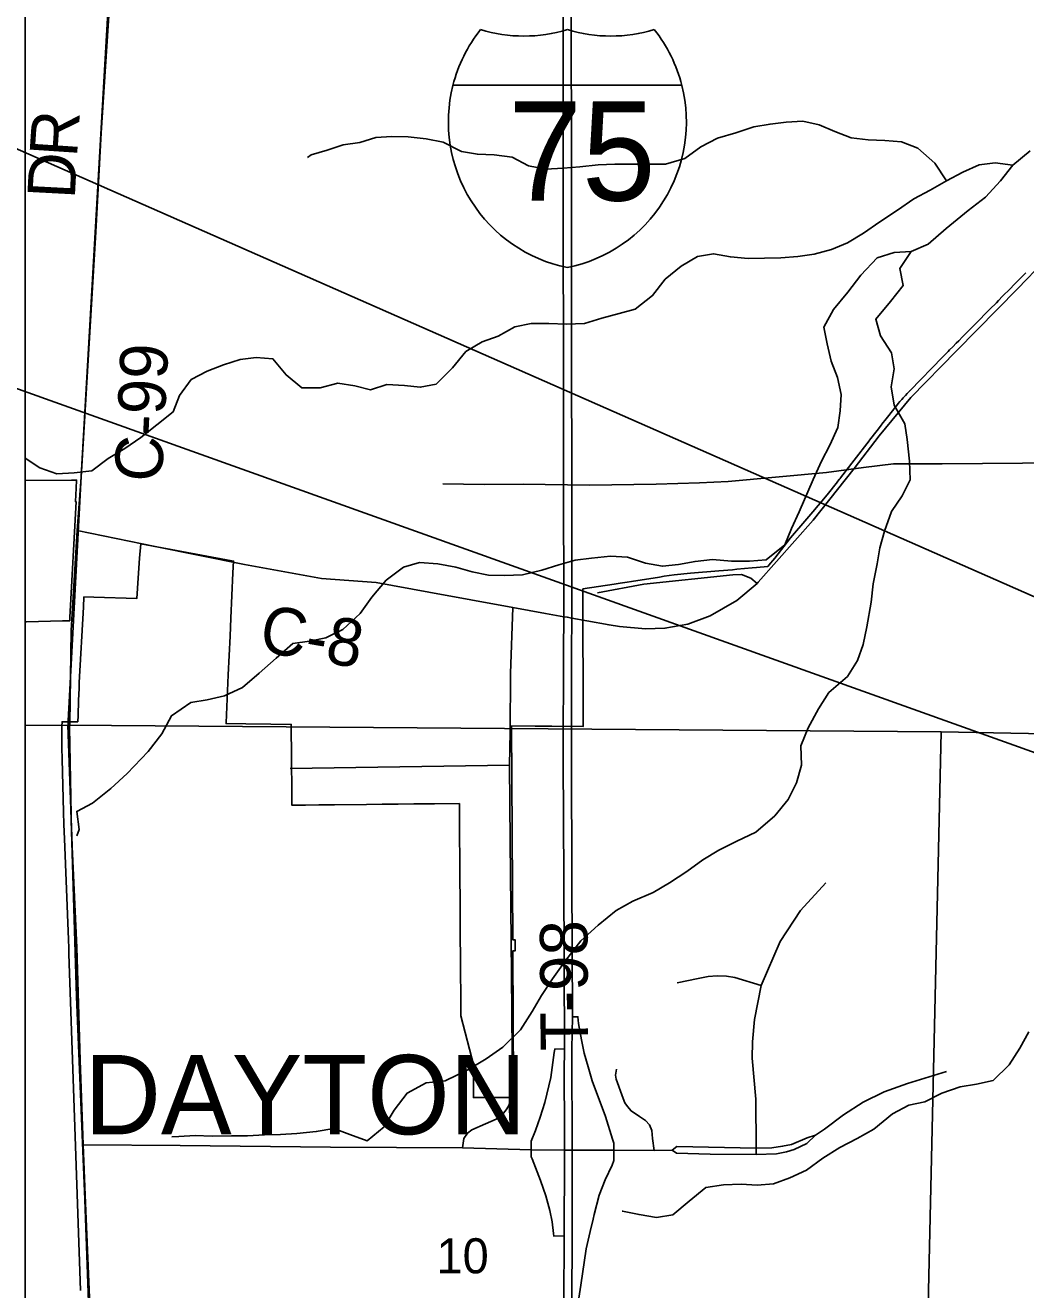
# Model space of a CAD drawing. Extents: x -38.1 to 35.9, y -2.7 to 28.5.
# Drawn here: x 8.115 to 9.309, y 16.206 to 17.716 of the extents above; entities that cross this region are included whole.
import ezdxf

# ---------------------------------------------------------------- set-up
doc = ezdxf.new("R2010")
doc.units = 0
for name, color, linetype in [('GM_X_City_Street', 7, 'Continuous'), ('GM_X_City_Street_Text', 7, 'Continuous'), ('GM_X_Corporation', 7, 'Continuous'), ('GM_X_Corporation_Text', 7, 'Continuous'), ('GM_X_Interstate_Route', 7, 'Continuous'), ('GM_X_Major_River_Text', 7, 'Continuous'), ('GM_X_Minor_Lake', 7, 'Continuous'), ('GM_X_Minor_River', 7, 'Continuous'), ('GM_X_Rail_Line_Text', 7, 'Continuous'), ('GM_X_Section', 7, 'Continuous'), ('GM_X_State_Route', 7, 'Continuous'), ('GM_X_Township', 7, 'Continuous'), ('GM_X_Township_Subdivision', 7, 'Continuous'), ('GM_X_US_Route', 7, 'Continuous'), ('SH_Data', 7, 'Continuous')]:
    doc.layers.add(name, color=color, linetype=linetype)

msp = doc.modelspace()

# ---------------------------------------------------------------- linework, layer by layer
at = {"layer": 'GM_X_City_Street'}
for points in [[(8.798, 17.0381), (8.8534, 17.0482), (8.9596, 17.0594), (8.9699, 17.0598), (8.981, 17.0557), (8.9885, 17.0492)], [(8.9876, 16.3675), (8.9876, 16.3751), (8.9871, 16.4337), (8.9828, 16.4825), (8.9832, 16.5018), (8.9855, 16.5288), (8.9933, 16.5692), (9.0162, 16.6217), (9.0403, 16.6586), (9.0705, 16.6917)], [(8.8931, 16.5725), (8.9183, 16.5775), (8.9302, 16.5798), (8.9408, 16.5808), (8.9522, 16.5802), (8.962, 16.5786), (8.9933, 16.5692)], [(8.8656, 16.3723), (8.8638, 16.3864), (8.8627, 16.3963), (8.86, 16.4027), (8.8554, 16.4079), (8.8481, 16.4128), (8.838, 16.4195), (8.8339, 16.4247), (8.8306, 16.4292), (8.8285, 16.4342), (8.8203, 16.4573), (8.8196, 16.4622), (8.8206, 16.4695)], [(9.0585, 16.3907), (9.069, 16.3978), (9.0917, 16.4148), (9.1153, 16.4299), (9.1404, 16.4422), (9.1683, 16.4522), (9.2147, 16.4664)], [(8.1838, 16.379), (8.2995, 16.3784), (8.4793, 16.3764), (8.6368, 16.3753)], [(8.8873, 16.3728), (8.8923, 16.3689), (8.9327, 16.368), (8.9876, 16.3675), (9.0117, 16.3684), (9.0235, 16.3708), (9.033, 16.3736), (9.0481, 16.3807), (9.0585, 16.3907)], [(8.8873, 16.3728), (8.8926, 16.377), (8.9876, 16.3751), (9.0061, 16.3756), (9.019, 16.3773), (9.0297, 16.3796), (9.0483, 16.3872), (9.0585, 16.3907)], [(8.6368, 16.3753), (8.7187, 16.3731), (8.7587, 16.3728), (8.7629, 16.3727), (8.7677, 16.3727), (8.8175, 16.3727)], [(8.8175, 16.3727), (8.8656, 16.3723), (8.8873, 16.3728)]]:
    msp.add_lwpolyline(points, dxfattribs=at)
at = {"layer": 'GM_X_City_Street_Text'}
for points in [[(8.1677, 16.8817), (8.1695, 16.9932), (8.1765, 17.1126), (8.1815, 17.1762), (8.1988, 17.4691), (8.2052, 17.587), (8.2104, 17.6664), (8.2151, 17.7391), (8.2187, 17.7863), (8.2231, 17.868), (8.2231, 17.8756)], [(8.9898, 17.0507), (9.0554, 17.1249), (9.1046, 17.1865), (9.1345, 17.2256), (9.1723, 17.2711), (9.2266, 17.3269), (9.3001, 17.4015), (9.3314, 17.4339), (9.3361, 17.4389)], [(8.1765, 17.1126), (8.2697, 17.0932), (8.3766, 17.0717), (8.4684, 17.055), (8.5336, 17.0502), (8.5967, 17.0387)], [(8.7852, 17.0046), (8.8119, 16.9997), (8.8241, 16.9977), (8.8552, 16.9952), (8.8785, 16.9958), (8.906, 17.0008), (8.9325, 17.0106), (8.9643, 17.0288), (8.9885, 17.0492), (8.9898, 17.0507)], [(8.5967, 17.0387), (8.6968, 17.0205), (8.736, 17.0133)], [(8.736, 17.0133), (8.7576, 17.0093), (8.7619, 17.009), (8.7674, 17.0079), (8.7852, 17.0046)], [(8.1924, 16.1683), (8.1862, 16.3191), (8.1838, 16.379), (8.18, 16.4801), (8.1761, 16.6146), (8.17, 16.7523), (8.1676, 16.8777), (8.1677, 16.8817)]]:
    msp.add_lwpolyline(points, dxfattribs=at)
at = {"layer": 'GM_X_Corporation'}
for points in [[(8.1169, 12.9308), (8.1202, 13.4509), (8.1267, 14.3761), (8.1272, 14.5808), (8.1295, 14.9033), (8.1448, 15.2944), (8.1561, 15.4105), (8.2031, 15.8872), (8.1758, 16.5559), (8.1657, 16.8852), (8.1819, 17.1843), (8.2212, 17.8697), (8.2224, 17.8749)], [(9.4498, 17.1939), (9.2095, 17.1922), (9.1516, 17.1919), (9.1158, 17.1876), (9.0714, 17.1817), (8.954, 17.1708), (8.9198, 17.1692), (8.8679, 17.1679), (8.7886, 17.1666), (8.7094, 17.1679), (8.6627, 17.1675), (8.6134, 17.1682)]]:
    msp.add_lwpolyline(points, dxfattribs=at)
at = {"layer": 'GM_X_Corporation_Text'}
msp.add_line((8.767, 16.8614), (8.767, 16.8813), dxfattribs=at)
for points in [[(8.7584, 16.4935), (8.7576, 16.6966), (8.7571, 16.8386), (8.7573, 16.969), (8.7576, 17.0093), (8.7576, 17.0139), (8.7575, 17.1756), (8.7573, 17.3174), (8.7571, 17.4714), (8.7571, 17.6068), (8.7568, 17.6716), (8.7567, 17.7848), (8.7566, 17.8702)], [(8.767, 16.8813), (8.7671, 16.9689), (8.7674, 17.0079), (8.7675, 17.0138), (8.7673, 17.1755), (8.7671, 17.3173), (8.767, 17.4713), (8.767, 17.6067), (8.7666, 17.6715), (8.7665, 17.7847), (8.7664, 17.8701)], [(8.7675, 16.191), (8.7679, 16.2705), (8.7678, 16.3654), (8.7677, 16.3727), (8.7676, 16.3973), (8.7673, 16.4664), (8.7675, 16.4935), (8.7683, 16.5318), (8.7675, 16.6965), (8.767, 16.8385), (8.767, 16.8614)], [(8.7594, 15.2455), (8.7597, 15.3293), (8.7594, 15.4349), (8.759, 15.5044), (8.759, 15.5824), (8.7589, 15.6629), (8.7589, 15.712), (8.7588, 15.7195), (8.7585, 15.7349), (8.7589, 15.8455), (8.759, 15.8997), (8.7587, 15.9265), (8.759, 16.0287), (8.758, 16.1522), (8.7577, 16.1907), (8.7582, 16.2702), (8.7587, 16.3653), (8.7587, 16.3728), (8.7586, 16.3972), (8.7582, 16.4663), (8.7584, 16.4935)]]:
    msp.add_lwpolyline(points, dxfattribs=at)
at = {"layer": 'GM_X_Interstate_Route'}
for p, q in [((8.6254, 17.6439), (8.8986, 17.6439)), ((8.8986, 17.6439), (8.6254, 17.6439)), ((8.8986, 17.6439), (8.6254, 17.6439))]:
    msp.add_line(p, q, dxfattribs=at)
for centre, start, end in [((8.7975, 17.6003), 141.669, 165.8066), ((8.7101, 17.8803), 253.0091, 286.9909), ((8.8139, 17.8803), 253.0091, 286.9909), ((8.7265, 17.6003), 14.1934, 38.331), ((8.7975, 17.6003), 165.8066, 258.463), ((8.7265, 17.6003), 281.537, 14.1934)]:
    msp.add_arc(centre, 0.1776, start, end, dxfattribs=at)
at = {"layer": 'GM_X_Major_River_Text'}
msp.add_line((8.4309, 16.8281), (8.6929, 16.8323), dxfattribs=at)
for points in [[(8.696, 16.4401), (8.6962, 16.4889), (8.6953, 16.5831), (8.6936, 16.741), (8.6929, 16.8323), (8.6936, 16.8715), (8.6941, 16.9419), (8.6968, 17.0205)], [(8.6368, 16.3753), (8.6384, 16.3865), (8.6426, 16.3931), (8.6478, 16.397), (8.6643, 16.4041), (8.677, 16.4096), (8.6841, 16.4149), (8.6891, 16.4209), (8.6918, 16.4253), (8.6959, 16.4369), (8.696, 16.4401)]]:
    msp.add_lwpolyline(points, dxfattribs=at)
at = {"layer": 'GM_X_Rail_Line_Text'}
for points in [[(8.8175, 16.3727), (8.8175, 16.3808), (8.816, 16.3859), (8.8076, 16.4129), (8.7917, 16.4554), (8.7867, 16.4723), (8.782, 16.4885), (8.7788, 16.5042), (8.7754, 16.5238), (8.7746, 16.5319), (8.7683, 16.5318)], [(8.7584, 16.4935), (8.7469, 16.4934), (8.7464, 16.4891), (8.7422, 16.4593), (8.7351, 16.4296), (8.7295, 16.4121), (8.7239, 16.3963), (8.7186, 16.3834), (8.7187, 16.3731)], [(8.7187, 16.3731), (8.7188, 16.3648), (8.7201, 16.3621), (8.7301, 16.3366), (8.7362, 16.3181), (8.7409, 16.3008), (8.7438, 16.2872), (8.7456, 16.2733), (8.7459, 16.2698), (8.7582, 16.2702)], [(8.7929, 16.2904), (8.7942, 16.2957), (8.8001, 16.3189), (8.8073, 16.3371), (8.8155, 16.3548), (8.8174, 16.3603), (8.8175, 16.3727)], [(8.7675, 16.191), (8.7749, 16.1906), (8.7779, 16.2116), (8.7846, 16.2547), (8.7892, 16.2756), (8.7929, 16.2904)]]:
    msp.add_lwpolyline(points, dxfattribs=at)
at = {"layer": 'GM_X_Section'}
msp.add_line((8.132, 17.1873), (8.1146, 17.1986), dxfattribs=at)
for points in [[(9.2147, 17.5299), (9.201, 17.5508), (9.1804, 17.569), (9.1611, 17.5763), (9.1413, 17.5782), (9.1211, 17.5789), (9.101, 17.5812), (9.0816, 17.5888), (9.0626, 17.5968), (9.0432, 17.601), (9.0234, 17.5999), (9.004, 17.5976), (8.9846, 17.5942), (8.9633, 17.5873), (8.9413, 17.5809), (8.9215, 17.5706), (8.9021, 17.5566), (8.8793, 17.5497), (8.8188, 17.5497), (8.7987, 17.549), (8.777, 17.5467), (8.7568, 17.5452), (8.7363, 17.5437), (8.7154, 17.5479), (8.696, 17.5581), (8.6747, 17.5608), (8.6545, 17.5616), (8.6355, 17.565), (8.6138, 17.576), (8.5933, 17.5802), (8.572, 17.5825), (8.5522, 17.5829), (8.5332, 17.5817), (8.5142, 17.5756), (8.4944, 17.573), (8.475, 17.5665), (8.456, 17.5608), (8.4518, 17.5578)], [(9.3147, 17.5656), (9.2941, 17.5485), (9.2728, 17.5515), (9.2538, 17.5489), (9.2344, 17.5401), (9.2147, 17.5299), (9.1953, 17.5189), (9.1759, 17.5082), (9.1561, 17.4949), (9.1352, 17.4809), (9.1158, 17.4676), (9.0964, 17.4558), (9.0774, 17.4478), (9.0568, 17.4425), (9.0371, 17.4395), (9.0169, 17.438), (8.9781, 17.4372), (8.9568, 17.4391), (8.9367, 17.4429), (8.9173, 17.4395), (8.8979, 17.4281), (8.8789, 17.4125), (8.8637, 17.3928), (8.8431, 17.3768), (8.8237, 17.3715), (8.8032, 17.3658), (8.7823, 17.3594), (8.761, 17.3586), (8.7397, 17.3597), (8.7188, 17.3594), (8.6994, 17.3556), (8.6792, 17.3446), (8.6602, 17.3377), (8.6408, 17.3263), (8.6249, 17.3066), (8.6055, 17.2872), (8.5864, 17.2834), (8.5674, 17.2857), (8.5465, 17.2868), (8.5271, 17.2804), (8.5081, 17.2853), (8.488, 17.2883), (8.4667, 17.2827), (8.445, 17.2827), (8.426, 17.2982), (8.4104, 17.3172), (8.3902, 17.3191), (8.3712, 17.3165), (8.3514, 17.3104), (8.3317, 17.3028), (8.3126, 17.2926), (8.299, 17.2736), (8.2913, 17.2542), (8.2716, 17.2386), (8.2526, 17.2234), (8.2335, 17.2105), (8.2138, 17.1983), (8.194, 17.1835), (8.1731, 17.1812), (8.1525, 17.1801), (8.132, 17.1873)], [(9.2941, 17.5485), (9.2793, 17.5299), (9.2614, 17.5105), (9.2405, 17.4945), (9.2143, 17.4729), (9.193, 17.4543), (9.1725, 17.4455), (9.1523, 17.4444), (9.1321, 17.4379), (9.1124, 17.4174), (9.0968, 17.3969), (9.08, 17.3764), (9.0683, 17.3551), (9.0721, 17.3353), (9.077, 17.3144), (9.0846, 17.295), (9.0888, 17.2749), (9.0876, 17.2551), (9.085, 17.2354), (9.0755, 17.2145), (9.0656, 17.1951), (9.0557, 17.1735), (9.039, 17.1347), (9.0298, 17.1149), (9.0215, 17.0952), (8.9994, 17.0773), (8.9796, 17.0758), (8.958, 17.0758), (8.9352, 17.0777), (8.9146, 17.0755), (8.8948, 17.072), (8.8755, 17.0698), (8.8553, 17.0736), (8.834, 17.0804), (8.8135, 17.0816), (8.7907, 17.0793), (8.7713, 17.077), (8.7519, 17.0713), (8.7317, 17.0649), (8.7085, 17.0596), (8.6868, 17.0588), (8.6678, 17.0592), (8.6484, 17.063), (8.6287, 17.0687), (8.6074, 17.0725), (8.5853, 17.0744), (8.5663, 17.0687), (8.5458, 17.0531), (8.5286, 17.033), (8.5146, 17.0132), (8.494, 16.9943), (8.4735, 16.9844), (8.4541, 16.9802), (8.434, 16.9775), (8.4142, 16.9601), (8.394, 16.9422), (8.3739, 16.9251), (8.3526, 16.9149), (8.3317, 16.9103), (8.3123, 16.9069), (8.2894, 16.8913), (8.2777, 16.8697), (8.2613, 16.8484), (8.2362, 16.8222), (8.2168, 16.8043), (8.1951, 16.7869), (8.1761, 16.777), (8.1788, 16.7553), (8.1761, 16.7481)], [(9.1725, 17.4455), (9.1591, 17.4254), (9.1629, 17.4049), (9.1477, 17.3859), (9.1302, 17.3646), (9.1359, 17.3448), (9.1492, 17.3247), (9.1523, 17.3053), (9.1485, 17.284), (9.1523, 17.262), (9.1652, 17.2399), (9.1679, 17.2209), (9.1705, 17.1951), (9.1713, 17.173), (9.1618, 17.154), (9.1492, 17.135), (9.1409, 17.1115), (9.1352, 17.0917), (9.1318, 17.0727), (9.1272, 17.0488), (9.1249, 17.0268), (9.1196, 16.9975), (9.1154, 16.9762), (9.1086, 16.9572), (9.0964, 16.9382), (9.0743, 16.9189), (9.0618, 16.8995), (9.0496, 16.8767), (9.0409, 16.8554), (9.0416, 16.8322), (9.0356, 16.8113), (9.0257, 16.7912), (9.0097, 16.7718), (8.9869, 16.7521), (8.9644, 16.7414), (8.9428, 16.7308), (8.9238, 16.7194), (8.9047, 16.7054), (8.8838, 16.6917), (8.8644, 16.6803), (8.8401, 16.6701), (8.8203, 16.6587), (8.7987, 16.6412), (8.7781, 16.6226), (8.7602, 16.5994), (8.7443, 16.577), (8.7313, 16.5573), (8.7199, 16.5383), (8.7059, 16.5162), (8.685, 16.4957), (8.6652, 16.4817), (8.6431, 16.4684), (8.6161, 16.4555), (8.5933, 16.4532), (8.5705, 16.4407), (8.5553, 16.4202), (8.5431, 16.4004), (8.523, 16.3837), (8.5024, 16.3913), (8.483, 16.3985), (8.4621, 16.3948), (8.4389, 16.3925), (8.4195, 16.3913), (8.4005, 16.391), (8.38, 16.3898), (8.361, 16.3898), (8.3378, 16.3895), (8.3176, 16.3902), (8.2982, 16.3891), (8.2895, 16.3887)], [(9.3132, 16.5141), (9.3025, 16.4944), (9.2896, 16.4746), (9.2706, 16.456), (9.2504, 16.4515), (9.231, 16.4481), (9.209, 16.4408), (9.1888, 16.4302), (9.1698, 16.4264), (9.1504, 16.4162), (9.128, 16.3976), (9.1082, 16.3865), (9.0873, 16.3759), (9.0671, 16.363), (9.0474, 16.3486), (9.0276, 16.3395), (9.0082, 16.3326), (8.9888, 16.3307), (8.9694, 16.3319), (8.9485, 16.3311), (8.9272, 16.3281), (8.9074, 16.3118), (8.888, 16.2954), (8.8686, 16.2924), (8.8477, 16.2958), (8.828, 16.3), (8.8276, 16.3)]]:
    msp.add_lwpolyline(points, dxfattribs=at)
at = {"layer": 'GM_X_US_Route'}
for points in [[(8.1146, 17.8763), (8.1146, 12.9308), (14.9146, 12.9308)], [(8.1146, 17.8763), (8.1146, 12.9308)], [(9.3096, 17.4202), (9.3021, 17.4126), (9.2957, 17.4062), (9.2908, 17.4011), (9.2817, 17.392), (9.2769, 17.387), (9.2743, 17.3843), (9.2665, 17.3765), (9.2612, 17.3713), (9.254, 17.364), (9.2465, 17.3565), (9.2394, 17.3493), (9.2339, 17.3435), (9.2295, 17.339), (9.2265, 17.336), (9.2224, 17.3319), (9.2185, 17.328), (9.2168, 17.3263), (9.2099, 17.3192), (9.1712, 17.2796), (9.171, 17.2793), (9.1679, 17.2761), (9.1657, 17.2738), (9.1656, 17.2738), (9.1634, 17.2714), (9.163, 17.271), (9.1613, 17.269), (9.1591, 17.2665), (9.1571, 17.264), (9.1549, 17.2614), (9.1523, 17.258), (9.1518, 17.2574), (9.1426, 17.2457), (9.1375, 17.2392), (9.137, 17.2385), (9.1319, 17.232), (9.1229, 17.2204), (9.1223, 17.2196), (9.1044, 17.1965), (9.0881, 17.1753), (9.0876, 17.1746), (9.0869, 17.1737), (9.0846, 17.1708), (9.0846, 17.1707), (9.0722, 17.1551), (9.0553, 17.1349), (9.048, 17.1264), (9.0283, 17.1036), (9.0245, 17.0986), (9.0097, 17.0794), (9.0073, 17.0765), (9.0046, 17.0734), (9.0012, 17.0693), (8.988, 17.0682), (8.9828, 17.0678), (8.9643, 17.0662), (8.9591, 17.0656), (8.9428, 17.0642), (8.9092, 17.0613), (8.8894, 17.0596), (8.8775, 17.0578), (8.8722, 17.0569), (8.8386, 17.0517), (8.8334, 17.0509), (8.8251, 17.0496), (8.8178, 17.0484), (8.7806, 17.0426), (8.7809, 16.8785), (8.7436, 16.8788), (8.7406, 16.8788), (8.7361, 16.8788), (8.7298, 16.8789), (8.7236, 16.8789), (8.6953, 16.8792), (8.6967, 16.6238), (8.6995, 16.6238), (8.6996, 16.6106), (8.6968, 16.6105), (8.6973, 16.5281), (8.6977, 16.4532), (8.6987, 16.4534), (8.7008, 16.4539), (8.7008, 16.4538), (8.701, 16.438), (8.701, 16.4357), (8.6933, 16.4356), (8.6922, 16.4356), (8.6905, 16.4356), (8.6893, 16.4356), (8.6754, 16.4356), (8.6522, 16.4355), (8.6498, 16.4355), (8.65, 16.4544), (8.6503, 16.4733), (8.6349, 16.5331), (8.6347, 16.5616), (8.6345, 16.5806), (8.6335, 16.7188), (8.6333, 16.7491), (8.633, 16.7865), (8.6034, 16.7862), (8.5977, 16.7862), (8.5788, 16.786), (8.5599, 16.7858), (8.5409, 16.7856), (8.522, 16.7854), (8.4841, 16.7851), (8.4652, 16.7849), (8.4491, 16.7847), (8.4376, 16.7846), (8.4372, 16.7846), (8.4371, 16.7846), (8.433, 16.7845), (8.433, 16.7854), (8.4328, 16.8095), (8.4326, 16.8303), (8.4326, 16.835), (8.4326, 16.8398), (8.4322, 16.881), (8.4077, 16.8813), (8.3781, 16.8817), (8.3544, 16.8819), (8.3545, 16.8829), (8.3571, 16.9402), (8.3592, 16.9862), (8.3602, 17.0077), (8.3627, 17.0618), (8.3633, 17.076), (8.3612, 17.0764), (8.2654, 17.0942), (8.2525, 17.0966), (8.2512, 17.0796), (8.2495, 17.0557), (8.2477, 17.0311), (8.1964, 17.0327), (8.1846, 17.0331), (8.184, 17.0209), (8.1791, 16.9311), (8.179, 16.9298), (8.1789, 16.927), (8.1788, 16.9241), (8.1783, 16.9094), (8.1777, 16.8917), (8.1774, 16.8842), (8.1621, 16.8842), (8.1586, 16.8841), (8.1584, 16.8789), (8.1582, 16.8661), (8.1584, 16.853), (8.1585, 16.8396), (8.1601, 16.7767), (8.1607, 16.7613), (8.1614, 16.7442), (8.1662, 16.624), (8.1666, 16.6137), (8.1668, 16.6069), (8.1748, 16.3775), (8.1807, 16.2052)], [(9.1857, 15.8712), (9.2082, 16.8722), (9.8961, 16.8589)]]:
    msp.add_lwpolyline(points, dxfattribs=at)
for points in [[(8.1146, 17.1721), (8.1146, 17.0034), (8.1161, 17.0034), (8.1591, 17.0044), (8.161, 17.0045), (8.1677, 17.0046), (8.1679, 17.0085), (8.1754, 17.1469), (8.1745, 17.1469), (8.1753, 17.1629), (8.1759, 17.1727), (8.1747, 17.1727), (8.1698, 17.1726)], [(8.1146, 16.8798), (8.1146, 15.8757), (8.2, 15.8756), (8.1963, 16.0249), (8.1654, 16.8799)], [(8.1654, 16.8799), (9.2082, 16.8722), (9.1857, 15.8712), (9.1505, 15.8719), (8.2, 15.8756), (8.1963, 16.0249)]]:
    msp.add_lwpolyline(points, close=True, dxfattribs=at)
at = {"layer": 'SH_Data'}
msp.add_lwpolyline([(7.839, 17.3766), (11.5732, 16.0414), (7.839, 17.6847)], close=True, dxfattribs=at)

# ---------------------------------------------------------------- texts
at = {"layer": 'GM_X_Interstate_Route'}
msp.add_text('75', height=0.11837, dxfattribs=at).set_placement((8.6913, 17.5063))
at = {"layer": 'GM_X_Minor_Lake'}
msp.add_text('T-98', height=0.05682, rotation=90.3538, dxfattribs=at).set_placement((8.7869, 16.4912))
at = {"layer": 'GM_X_Minor_River'}
msp.add_text('10', height=0.04186, rotation=0, dxfattribs=at).set_placement((8.6058, 16.2256))
at = {"layer": 'GM_X_State_Route'}
for s in ['-', '.', ',']:
    msp.add_text(s, height=0.000189, dxfattribs=at).set_placement((8.762, 17.5683))
msp.add_text('75', height=0.000189, rotation=0, dxfattribs=at).set_placement((8.7233, 17.5291))
at = {"layer": 'GM_X_Township'}
for s, height, rotation, p in [('R', 0.0568, 86.1722, (8.1763, 17.5572)), ('D', 0.0568, 87.0006, (8.1737, 17.5075)), ('C-99', 0.05682, 87.2908, (8.2778, 17.1697)), ('C-8', 0.05682, 350.3148, (8.3922, 16.9684))]:
    msp.add_text(s, height=height, rotation=rotation, dxfattribs=at).set_placement(p)
at = {"layer": 'GM_X_Township_Subdivision'}
msp.add_text('DAYTON', height=0.0947, rotation=0, dxfattribs=at).set_placement((8.1852, 16.3916))

doc.saveas('drawing.dxf')
